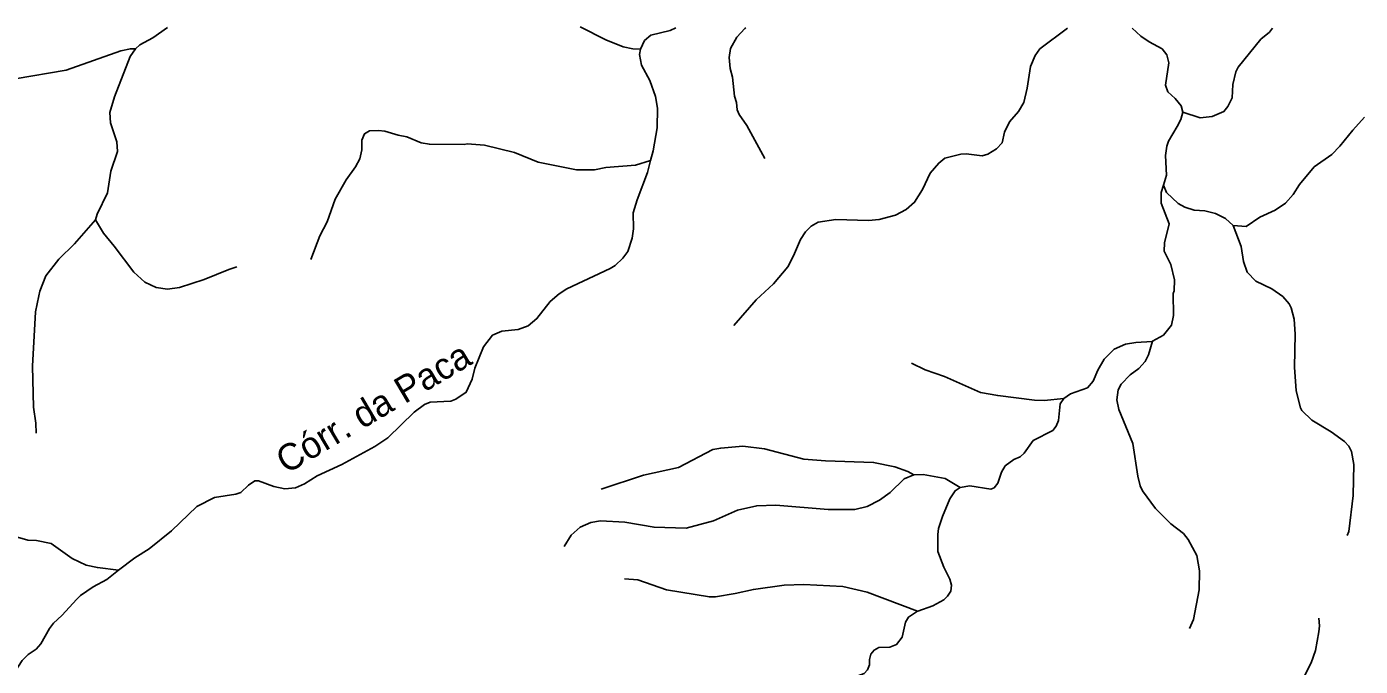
# Model space of a CAD drawing. Extents: x 500 to 555.2, y 9115.7 to 9171.
# Drawn here: x 517.83 to 525.89, y 9167.11 to 9170.98 of the extents above; entities that cross this region are included whole.
import ezdxf
from ezdxf.enums import TextEntityAlignment as Align

# ---------------------------------------------------------------- set-up
doc = ezdxf.new("R2010")
doc.units = 0
doc.header["$LTSCALE"] = 0.064
doc.layers.add('61', color=7, linetype='Continuous')
doc.layers.add('7', color=7, linetype='Continuous', lineweight=25)

msp = doc.modelspace()

# ---------------------------------------------------------------- linework, layer by layer
at = {"layer": '7'}
for points in [[(518.484, 9170.8424), (518.5108, 9170.867), (518.588, 9170.9093), (518.6772, 9170.9708)], [(521.1748, 9170.9766), (521.3302, 9170.8968), (521.4345, 9170.8552), (521.4934, 9170.8425), (521.5388, 9170.8411)], [(521.5388, 9170.8411), (521.5636, 9170.8929), (521.6013, 9170.926), (521.719, 9170.9544), (521.7522, 9170.9694)], [(522.2921, 9170.179), (522.1829, 9170.3791), (522.1369, 9170.4453), (522.125, 9170.4746), (522.1205, 9170.5175), (522.1076, 9170.557), (522.0964, 9170.6723), (522.0813, 9170.7242), (522.0764, 9170.7905), (522.0848, 9170.8448), (522.1227, 9170.9127), (522.1715, 9170.9648), (522.1757, 9170.9693)], [(522.1039, 9169.169), (522.24, 9169.3256), (522.3446, 9169.4222), (522.4303, 9169.5245), (522.4648, 9169.5913), (522.5065, 9169.6907), (522.5377, 9169.7366), (522.5713, 9169.7697), (522.6144, 9169.7938), (522.7218, 9169.8099), (522.9185, 9169.8051), (522.9841, 9169.8117), (523.0818, 9169.8379), (523.1475, 9169.8707), (523.1973, 9169.9154), (523.2458, 9169.992), (523.2919, 9170.0904), (523.3439, 9170.1522), (523.3805, 9170.1821), (523.4783, 9170.2054), (523.509, 9170.2068), (523.6074, 9170.1957), (523.6408, 9170.2059), (523.694, 9170.2372), (523.7282, 9170.2748), (523.7419, 9170.338), (523.7725, 9170.4021), (523.8265, 9170.4645), (523.859, 9170.5181), (523.8789, 9170.6049), (523.8987, 9170.7361), (523.9267, 9170.8023), (523.9562, 9170.843), (524.1238, 9170.9683)], [(524.8214, 9170.4595), (524.8099, 9170.4975), (524.775, 9170.5425), (524.7299, 9170.5832), (524.7153, 9170.6224), (524.7367, 9170.759), (524.724, 9170.8068), (524.6964, 9170.8417), (524.6173, 9170.8844), (524.5676, 9170.9195), (524.5133, 9170.9681)], [(525.363, 9170.9677), (525.3448, 9170.943), (525.2931, 9170.9006), (525.1552, 9170.7318), (525.1419, 9170.7033), (525.1229, 9170.6277), (525.1189, 9170.5465), (525.0928, 9170.494), (525.0689, 9170.4637), (524.9991, 9170.4338), (524.9252, 9170.4253), (524.8214, 9170.4595)], [(516.8033, 9170.148), (516.8673, 9170.258), (516.9037, 9170.293), (516.9665, 9170.3738), (517.0413, 9170.4517), (517.1167, 9170.5056), (517.299, 9170.5926), (517.354, 9170.612), (517.5147, 9170.6415), (517.7549, 9170.6609), (518.0643, 9170.7134), (518.3949, 9170.83), (518.4531, 9170.8432), (518.484, 9170.8424)], [(518.2426, 9169.8079), (518.2509, 9169.8437), (518.3148, 9169.9717), (518.3349, 9170.1036), (518.374, 9170.2211), (518.371, 9170.2801), (518.3324, 9170.3946), (518.3285, 9170.4586), (518.3557, 9170.5516), (518.4518, 9170.7966), (518.484, 9170.8424)], [(521.6003, 9170.1683), (521.6153, 9170.226), (521.6399, 9170.3646), (521.6418, 9170.4847), (521.6299, 9170.5545), (521.5957, 9170.6514), (521.5461, 9170.7448), (521.5334, 9170.8086), (521.5388, 9170.8411)], [(524.7033, 9170.019), (524.7221, 9170.078), (524.7156, 9170.1969), (524.7237, 9170.2539), (524.734, 9170.2846), (524.7861, 9170.3727), (524.8084, 9170.4162), (524.8214, 9170.4595)], [(525.9196, 9170.4296), (525.849, 9170.3512), (525.7708, 9170.2533), (525.7227, 9170.2037), (525.6162, 9170.1282), (525.5263, 9170.0221), (525.4893, 9169.962), (525.441, 9169.9088), (525.3797, 9169.8681), (525.2873, 9169.8249), (525.2041, 9169.7692), (525.1248, 9169.7751)], [(519.5437, 9169.5695), (519.5993, 9169.7127), (519.6425, 9169.7964), (519.6915, 9169.933), (519.7587, 9170.0511), (519.8157, 9170.1293), (519.8403, 9170.1768), (519.8537, 9170.2321), (519.8538, 9170.29), (519.87, 9170.3296), (519.8986, 9170.3464), (519.9545, 9170.3497), (519.9921, 9170.3445), (520.072, 9170.3201), (520.1254, 9170.3103), (520.2128, 9170.2743), (520.2623, 9170.2653), (520.4732, 9170.2644), (520.491, 9170.2691), (520.5952, 9170.2594), (520.7763, 9170.2165), (520.9206, 9170.1577), (521.1529, 9170.1102), (521.2605, 9170.1117), (521.33, 9170.1249), (521.5099, 9170.1396), (521.6003, 9170.1683)], [(518.3817, 9167.6896), (518.4796, 9167.7652), (518.5657, 9167.8196), (518.7011, 9167.9288), (518.8543, 9168.0756), (518.9615, 9168.1303), (519.0912, 9168.1498), (519.1208, 9168.1609), (519.1672, 9168.2049), (519.2049, 9168.2302), (519.2278, 9168.2301), (519.3209, 9168.1964), (519.3873, 9168.1813), (519.4509, 9168.188), (519.5066, 9168.2127), (519.5837, 9168.2601), (519.7317, 9168.3285), (519.9319, 9168.4383), (520.0101, 9168.49), (520.1691, 9168.6458), (520.2319, 9168.6915), (520.2661, 9168.706), (520.3924, 9168.7129), (520.4223, 9168.7248), (520.4847, 9168.7665), (520.5208, 9168.8457), (520.5375, 9168.9121), (520.589, 9169.0413), (520.6446, 9169.1111), (520.7002, 9169.1356), (520.7986, 9169.1457), (520.8592, 9169.1687), (520.9122, 9169.2117), (520.9936, 9169.3158), (521.0475, 9169.3617), (521.0944, 9169.3919), (521.3557, 9169.5144), (521.3863, 9169.5332), (521.4333, 9169.5771), (521.4617, 9169.6177), (521.4893, 9169.6975), (521.4973, 9169.7552), (521.4954, 9169.8509), (521.5195, 9169.9305), (521.5812, 9170.0944), (521.6003, 9170.1683)], [(524.6375, 9169.0748), (524.7044, 9169.1118), (524.7516, 9169.1726), (524.7649, 9169.2302), (524.7616, 9169.3631), (524.7678, 9169.3786), (524.7696, 9169.4449), (524.7483, 9169.5382), (524.7072, 9169.6186), (524.7093, 9169.6687), (524.7383, 9169.7853), (524.6898, 9169.9086), (524.6887, 9169.9733), (524.7033, 9170.019)], [(525.1248, 9169.7751), (525.1244, 9169.7751), (525.0792, 9169.8169), (525.0193, 9169.8464), (524.9545, 9169.8625), (524.8885, 9169.8666), (524.8338, 9169.8845), (524.7923, 9169.9067), (524.7219, 9169.9731), (524.7033, 9170.019)], [(517.8835, 9168.5178), (517.8804, 9168.5787), (517.8658, 9168.6753), (517.8609, 9168.9231), (517.8789, 9169.2533), (517.8986, 9169.35), (517.9055, 9169.3772), (517.9411, 9169.4699), (518.0204, 9169.5709), (518.1137, 9169.6643), (518.2426, 9169.8079)], [(519.097, 9169.5238), (519.0482, 9169.5092), (518.8986, 9169.4473), (518.7501, 9169.3987), (518.6766, 9169.3885), (518.6079, 9169.3991), (518.541, 9169.4324), (518.473, 9169.4914), (518.355, 9169.6502), (518.289, 9169.728), (518.2426, 9169.8079)], [(525.8149, 9167.8991), (525.8247, 9167.9236), (525.8523, 9168.1418), (525.8556, 9168.3288), (525.8405, 9168.4081), (525.825, 9168.4393), (525.7981, 9168.4681), (525.7183, 9168.5268), (525.6017, 9168.5979), (525.5412, 9168.6564), (525.5326, 9168.6711), (525.5063, 9168.775), (525.4964, 9168.9187), (525.5013, 9169.1168), (525.4947, 9169.208), (525.4771, 9169.2756), (525.4644, 9169.3009), (525.4254, 9169.346), (525.3585, 9169.3915), (525.2624, 9169.4385), (525.2102, 9169.4922), (525.1876, 9169.5571), (525.1731, 9169.6475), (525.1248, 9169.7751)], [(524.0999, 9168.7292), (524.142, 9168.7569), (524.2429, 9168.793), (524.2788, 9168.8335), (524.3059, 9168.9003), (524.344, 9168.9655), (524.4061, 9169.0261), (524.4737, 9169.0563), (524.5366, 9169.0671), (524.6358, 9169.0739), (524.6375, 9169.0748)], [(524.8617, 9167.3385), (524.8846, 9167.3911), (524.9205, 9167.5705), (524.9222, 9167.6858), (524.9064, 9167.7788), (524.8536, 9167.8755), (524.8242, 9167.9116), (524.7472, 9167.9708), (524.6554, 9168.0626), (524.5761, 9168.1697), (524.5631, 9168.1993), (524.5484, 9168.2592), (524.5187, 9168.4567), (524.4337, 9168.6628), (524.4223, 9168.721), (524.4299, 9168.7801), (524.4486, 9168.8148), (524.5028, 9168.8706), (524.5543, 9168.9106), (524.5921, 9168.9513), (524.6127, 9168.9924), (524.6375, 9169.0748)], [(523.1783, 9168.9414), (523.2618, 9168.9015), (523.3786, 9168.8609), (523.597, 9168.7651), (523.7006, 9168.7456), (523.9238, 9168.7176), (523.9826, 9168.716), (524.0999, 9168.7292)], [(523.4739, 9168.1895), (523.532, 9168.1997), (523.6598, 9168.1799), (523.6783, 9168.1891), (523.7016, 9168.2173), (523.723, 9168.2822), (523.7467, 9168.321), (523.7991, 9168.3591), (523.8358, 9168.3761), (523.8607, 9168.3976), (523.9159, 9168.4749), (524.0342, 9168.535), (524.0544, 9168.5601), (524.0687, 9168.5963), (524.079, 9168.6964), (524.0999, 9168.7292)], [(521.3003, 9168.18), (521.5582, 9168.2653), (521.7698, 9168.3103), (521.9772, 9168.4193), (522.0251, 9168.4284), (522.1594, 9168.4403), (522.2898, 9168.4242), (522.5274, 9168.3616), (522.6581, 9168.3518), (522.9498, 9168.3414), (523.078, 9168.3158), (523.1567, 9168.2879), (523.194, 9168.2658)], [(521.0779, 9167.8342), (521.1201, 9167.9023), (521.1738, 9167.9511), (521.2388, 9167.9779), (521.2978, 9167.9892), (521.4443, 9167.9811), (521.6214, 9167.95), (521.8152, 9167.945), (521.9808, 9167.988), (522.1261, 9168.0534), (522.2426, 9168.0795), (522.3584, 9168.0827), (522.6744, 9168.0565), (522.8355, 9168.0569), (522.9107, 9168.0759), (522.9845, 9168.1136), (523.0502, 9168.1594), (523.1353, 9168.2427), (523.194, 9168.2658)], [(523.194, 9168.2658), (523.2492, 9168.2697), (523.3831, 9168.2436), (523.4739, 9168.1895)], [(523.3663, 9168.0153), (523.4113, 9168.1215), (523.444, 9168.1708), (523.4739, 9168.1895)], [(517.3212, 9168.1359), (517.5273, 9168.0288), (517.6571, 9167.942), (517.7268, 9167.9028), (517.8315, 9167.8713), (517.8848, 9167.8695), (517.974, 9167.8513), (518.1014, 9167.7604), (518.1858, 9167.7207), (518.2528, 9167.7055), (518.3817, 9167.6896)], [(523.2158, 9167.4425), (523.2167, 9167.4431), (523.3082, 9167.4743), (523.3742, 9167.5106), (523.3975, 9167.5339), (523.416, 9167.5639), (523.4212, 9167.6005), (523.4117, 9167.636), (523.3739, 9167.7087), (523.3388, 9167.8027), (523.3378, 9167.9056), (523.3427, 9167.9417), (523.3663, 9168.0153)], [(517.6871, 9166.7128), (517.7201, 9166.9464), (517.7528, 9167.0762), (517.7981, 9167.1441), (517.8341, 9167.18), (517.8821, 9167.2118), (517.9109, 9167.2456), (517.9626, 9167.3379), (517.9872, 9167.3692), (518.0382, 9167.4157), (518.1286, 9167.514), (518.1515, 9167.538), (518.2279, 9167.5888), (518.3104, 9167.6345), (518.3817, 9167.6896)], [(521.4427, 9167.6377), (521.523, 9167.6317), (521.6962, 9167.5722), (521.9566, 9167.5284), (521.9927, 9167.5288), (522.1117, 9167.5487), (522.2229, 9167.5742), (522.4087, 9167.6004), (522.5278, 9167.6036), (522.7631, 9167.5907), (522.9108, 9167.5564), (523.2158, 9167.4425)], [(522.4068, 9166.8249), (522.5799, 9166.9231), (522.6244, 9166.9769), (522.6905, 9167.0233), (522.7446, 9167.0362), (522.8311, 9167.0442), (522.8921, 9167.0662), (522.9137, 9167.0874), (522.9241, 9167.1177), (522.9244, 9167.1504), (522.9323, 9167.1823), (522.9523, 9167.2067), (522.9818, 9167.2218), (523.0473, 9167.2238), (523.0889, 9167.2408), (523.1229, 9167.2847), (523.1421, 9167.376), (523.1609, 9167.4069), (523.2158, 9167.4425)], [(525.6433, 9167.4003), (525.6484, 9167.3542), (525.6442, 9167.3169), (525.6227, 9167.2055), (525.5974, 9167.1296), (525.5586, 9167.056), (525.5028, 9166.9783), (525.488, 9166.9399), (525.4884, 9166.9105), (525.5095, 9166.8259), (525.5094, 9166.7777), (525.499, 9166.7264), (525.4958, 9166.6716), (525.5213, 9166.6186), (525.5397, 9166.5962), (525.5807, 9166.5773), (525.6086, 9166.572), (525.686, 9166.5769), (525.7903, 9166.6206), (525.9164, 9166.6836)]]:
    msp.add_lwpolyline(points, dxfattribs=at)

# ---------------------------------------------------------------- texts
at = {"layer": '61'}
msp.add_text('Córr. da Paca', height=0.16, rotation=30.651, dxfattribs=at).set_placement((519.9635, 9168.6052), align=Align.CENTER)

doc.saveas('drawing.dxf')
